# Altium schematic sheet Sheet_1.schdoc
size 291 x 201 mm
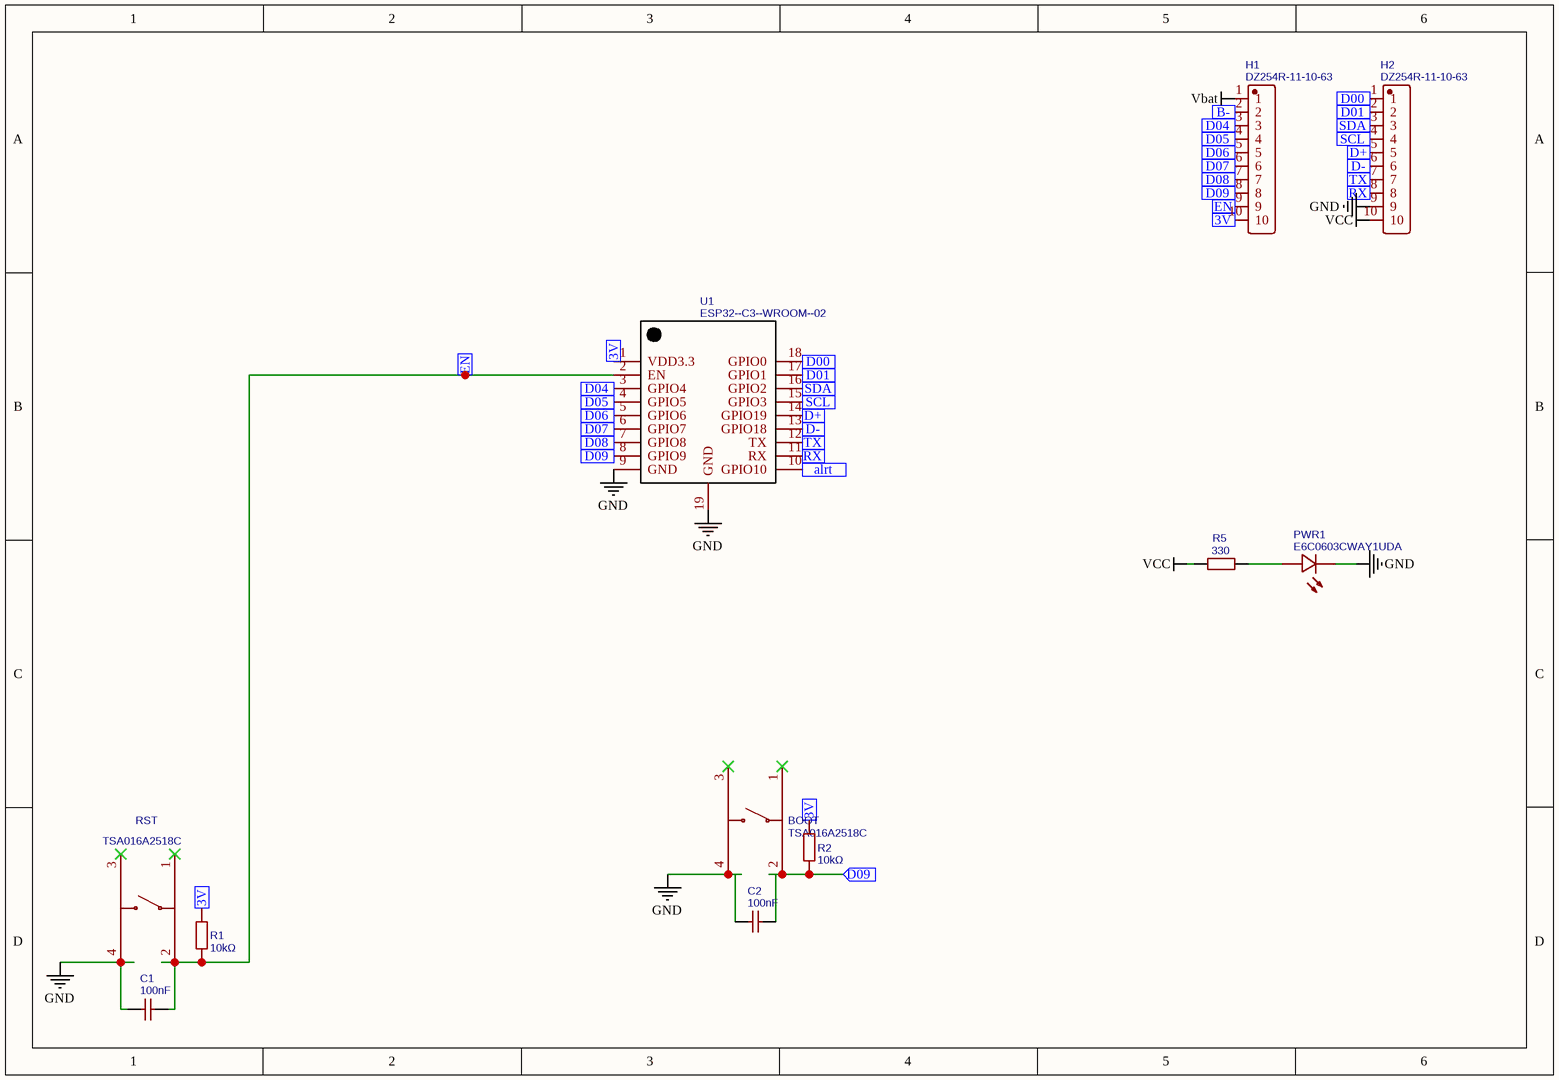
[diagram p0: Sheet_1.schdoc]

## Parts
BOOT  TSA016A2518C  [SW-SMD_4P-L4.2-W3.3-P2.15-LS4.6]
C1  100nF  [C0402]
C2  100nF  [C0402]
H1  DZ254R-11-10-63  [HDR-TH_10P-P2.54-V-M]
H2  DZ254R-11-10-63  [HDR-TH_10P-P2.54-V-M]
PWR1  E6C0603CWAY1UDA  [LED0603-R-RD_WHITE]
R1  10kΩ  [R0402]
R2  10kΩ  [R0402]
R5  330  [R0402]
RST  TSA016A2518C  [SW-SMD_4P-L4.2-W3.3-P2.15-LS4.6]
U1  ESP32-­C3­-WROOM­-02  [FOOTPRINT-ESP32-C3-WROOM-02]

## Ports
3V (in), alrt (in), B- (in), D00 (in), D01 (in), D04 (in), D05 (in), D06 (in), D07 (in), D08 (in), D09 (in), D+ (in), D- (in), EN (in), RX (in), SCL (in), SDA (in), TX (in)

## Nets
GND: BOOT.4 C1.1 C2.1 H2.9 PWR1.2(-) RST.4 U1.9(GND) U1.19(GND)
Vbat: H1.1
VCC: H2.10 R5.1
3V: H1.10 R1.2 R2.2 U1.1(VDD3.3) ; port 3V
alrt: U1.10(GPIO10) ; port alrt
B-: H1.2 ; port B-
D00: H2.1 U1.18(GPIO0) ; port D00
D01: H2.2 U1.17(GPIO1) ; port D01
D04: H1.3 U1.3(GPIO4) ; port D04
D05: H1.4 U1.4(GPIO5) ; port D05
D06: H1.5 U1.5(GPIO6) ; port D06
D07: H1.6 U1.6(GPIO7) ; port D07
D08: H1.7 U1.7(GPIO8) ; port D08
D09: BOOT.2 C2.2 H1.8 R2.1 U1.8(GPIO9) ; port D09
D+: H2.5 U1.14(GPIO19) ; port D+
D-: H2.6 U1.13(GPIO18) ; port D-
EN: C1.2 H1.9 R1.1 RST.2 U1.2(EN) ; port EN
RX: H2.8 U1.11(RX) ; port RX
SCL: H2.4 U1.15(GPIO3) ; port SCL
SDA: H2.3 U1.16(GPIO2) ; port SDA
TX: H2.7 U1.12(TX) ; port TX
NetPWR1_1: PWR1.1(+) R5.2

Not connected (* = marked no-connect by the designer): BOOT 1* 3*; RST 1* 3*

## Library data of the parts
BOOT RST = TSA016A2518C: Manufacturer: BZCN(博众电气); Contributor: LCSC
C1 C2 = 100nF: Manufacturer: FH(风华); Manufacturer Part: 0402B104K160NT; nameAlias: Capacitance
H1 H2 = DZ254R-11-10-63: Manufacturer: DEALON(德艺隆); Contributor: LCSC
PWR1 = E6C0603CWAY1UDA: Manufacturer: ekinglux(亿晶源); Contributor: LCSC
R1 R2 = 10kΩ: Manufacturer: 大毅科技; Manufacturer Part: RMS04FT1002; nameAlias: Value; Contributor: LCSC
R5 = 330: Manufacturer: UniOhm; Manufacturer Part: 0402WGF3300TCE; nameAlias: Resistance (Ohms)
U1 = ESP32-­C3­-WROOM­-02: Manufacturer: Espressif; Manufacturer Part: ESP32­-C3­-WROOM­-02; Contributor: daniel.nicoara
